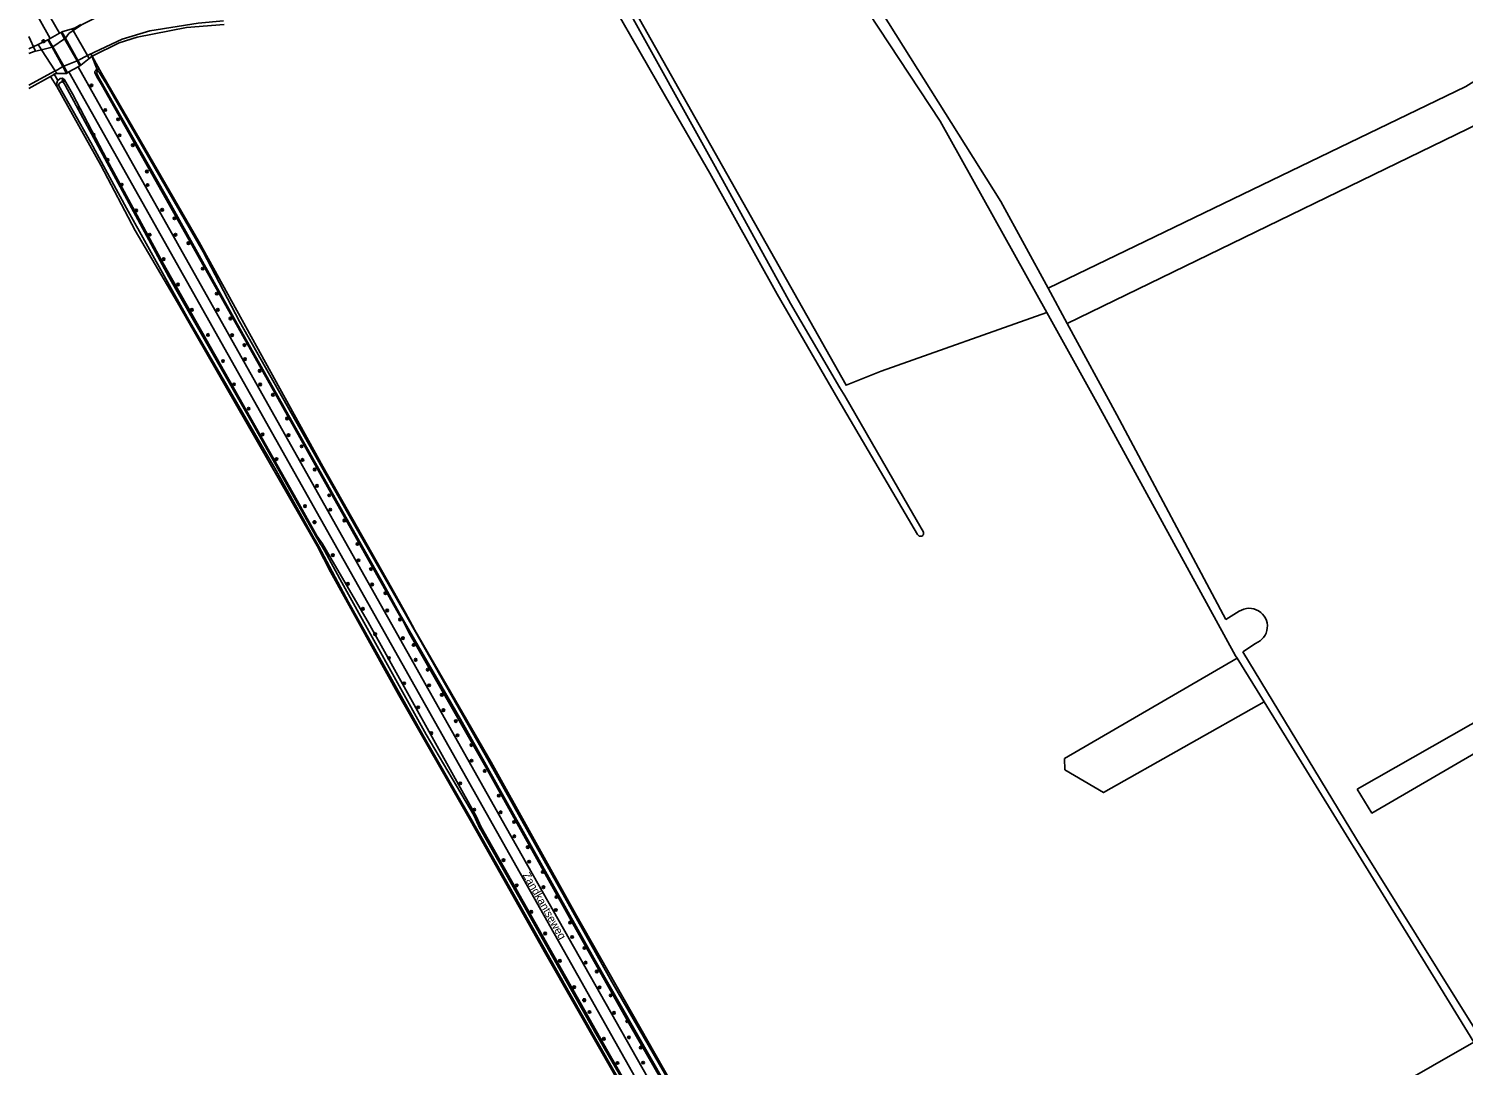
# Model space of a CAD drawing. Extents: x 140000 to 143000, y 403500 to 406000.
# Drawn here: x 140000 to 140448.3, y 404957.2 to 405281.2 of the extents above; entities that cross this region are included whole.
import ezdxf

# ---------------------------------------------------------------- set-up
doc = ezdxf.new("R2010")
doc.units = 0
for name, color, linetype in [('gg-anno-openbare ruimte label', 7, 'Continuous'), ('gg-knt-bronhoudergrens', 7, 'Continuous'), ('gg-knt-verharding', 7, 'Continuous'), ('gg-kntw-bovenkant insteek waterloop', 7, 'Continuous'), ('gg-kntw-waterlijn', 7, 'Continuous'), ('gg-kwrk-duiker nz buis', 7, 'Continuous'), ('gg-kwrk-kunstwerk niveau 01', 7, 'Continuous'), ('gt-grn-groengrens', 7, 'Continuous'), ('gt-grn-vlakafsluiter', 7, 'Continuous'), ('gt-symb-boom', 7, 'Continuous'), ('gt-symb-lichtmast', 7, 'Continuous')]:
    doc.layers.add(name, color=color, linetype=linetype)

# ---------------------------------------------------------------- blocks, each defined once
blk = doc.blocks.new('gt0-BOOM')
at = {"layer": 'gt-symb-boom'}
for radius in [0.4, 0.2]:
    blk.add_circle((0, 0), radius, dxfattribs=at)
blk = doc.blocks.new('gt0-LMAST')
at = {"layer": 'gt-symb-lichtmast'}
for p, q in [((-0.18, 0.17), (-0.45, 0.44)), ((-0.01, 0.25), (-0.01, 0.62)), ((0.17, 0.17), (0.44, 0.44)), ((-0.26, 0), (-0.63, 0)), ((-0.18, -0.18), (-0.45, -0.45)), ((-0.01, -0.25), (-0.01, -0.63)), ((0.44, -0.45), (0.17, -0.18)), ((0.24, 0), (0.62, 0))]:
    blk.add_line(p, q, dxfattribs=at)
blk.add_circle((-0.01, 0), 0.25, dxfattribs=at)

msp = doc.modelspace()

# ---------------------------------------------------------------- linework, layer by layer
at = {"layer": 'gg-knt-bronhoudergrens'}
msp.add_lwpolyline([(140318.13, 405192.44), (140266.36, 405174.11), (140255.39, 405169.74), (140185.81, 405293.12)], dxfattribs=at)
at = {"layer": 'gg-knt-verharding'}
msp.add_line((140000, 405296.57), (140009.61, 405279.74), dxfattribs=at)
for points in [[(140000, 405290.13), (140000.13, 405289.9), (140006.7, 405278.1)], [(140012.59, 405267.65), (140091.15, 405127.98), (140215.94, 404906.42), (140216.06, 404906.21)], [(140015.47, 405269.29), (140093.98, 405129.51), (140149.27, 405031.32), (140217.82, 404910.2), (140257.23, 404841.36), (140317.65, 404734.89), (140320.04, 404730.7)]]:
    msp.add_lwpolyline(points, dxfattribs=at)
at = {"layer": 'gg-kntw-bovenkant insteek waterloop'}
for p, q in [((140013.55, 405281.15), (140010.35, 405280.16)), ((140000, 405274.88), (140002.93, 405276.26)), ((140006, 405277.71), (140002.93, 405276.26)), ((140018.93, 405271.88), (140016.25, 405269.74)), ((140018.93, 405271.88), (140019.85, 405272.61)), ((140008.79, 405267.16), (140011.83, 405267.22)), ((140000, 405262.5), (140006.86, 405266.27)), ((140324.5, 405189.04), (140318.52, 405200.05)), ((140378.27, 405099.07), (140374.07, 405096.51)), ((140383.36, 405089.05), (140379.37, 405086.39)), ((140377.62, 405084.38), (140386.05, 405070.72))]:
    msp.add_line(p, q, dxfattribs=at)
for points in [[(140185.79, 405289.85), (140214.49, 405238.1), (140238.07, 405195.27), (140253.46, 405168.97), (140254.97, 405166.39), (140274.97, 405131.7), (140279.57, 405123.84)], [(140259.14, 405291.24), (140284.8, 405252.29), (140318.13, 405192.44)], [(140318.52, 405200.05), (140303.79, 405227.18), (140262.3, 405293.17)], [(140182.97, 405287.93), (140199.02, 405259.94), (140212.81, 405235.99), (140233.91, 405198.18), (140252.83, 405165.48), (140277.77, 405123.12)], [(140016.26, 405282.49), (140014.56, 405281.47), (140013.55, 405281.15)], [(140061.04, 405282.49), (140049.32, 405281.51), (140033.9, 405278.48), (140028.3, 405276.8), (140019.85, 405272.61)], [(140008.79, 405267.16), (140008.45, 405267.15), (140006.86, 405266.27)], [(140221.32, 404915.12), (140221.27, 404914.79), (140221.05, 404914.55), (140220.48, 404914.22), (140219.96, 404914.32), (140219.52, 404914.81), (140187.96, 404969.55), (140169.57, 405002.2), (140142.8, 405050.33), (140118.75, 405092.41), (140116.73, 405096.57), (140115.86, 405097.86), (140114.98, 405099.37), (140049.1, 405216.97), (140022.7, 405263.69), (140021.65, 405265.62), (140020.77, 405267.14)], [(140022.22, 405268.24), (140023.21, 405266.5), (140053.29, 405214.48), (140091.86, 405144.38), (140113.34, 405106.43), (140117.71, 405098.64), (140120.4, 405093.58), (140120.66, 405093.21), (140144.47, 405051.89), (140170.87, 405004.52), (140206.08, 404942.46), (140221.32, 404915.12)], [(140211.16, 404908.87), (140180.94, 404961.44), (140141.23, 405031.76), (140139.9, 405034.84), (140106.05, 405095.67), (140094.79, 405114.98), (140091.84, 405120.15), (140090.08, 405122.65), (140083.85, 405133.69), (140065.63, 405166.05), (140041.91, 405207.98), (140024.47, 405240.13), (140013.65, 405260.82), (140011.23, 405265.23), (140010.6, 405265.67), (140009.82, 405265.58), (140008.99, 405264.87), (140008.83, 405264.18), (140008.78, 405263.08)], [(140211.16, 404908.87), (140211.14, 404908.72), (140210.91, 404908.37), (140210.58, 404908.25), (140209.72, 404908.53), (140209.26, 404908.96), (140187.27, 404946.74), (140161.57, 404991.94), (140139.8, 405030.55), (140137.59, 405034.4), (140115.65, 405072.87), (140094.35, 405111.42), (140090.14, 405119.58), (140088.48, 405122.42), (140067.9, 405158.36), (140046.49, 405195.64), (140033.29, 405218.1), (140022.54, 405238.57), (140008.78, 405263.08)], [(140318.13, 405192.44), (140334.31, 405163.38), (140377.12, 405085.2), (140377.62, 405084.38)], [(140374.07, 405096.51), (140340, 405160.5), (140324.5, 405189.04)], [(140415.14, 405043.52), (140419.73, 405036), (140553.77, 405113.96), (140550.4, 405120.5), (140415.14, 405043.52)], [(140458.74, 404957.51), (140414.93, 405027.89), (140379.37, 405086.39)], [(140386.05, 405070.72), (140441.18, 404981.34), (140451.59, 404964.43)]]:
    msp.add_lwpolyline(points, dxfattribs=at)
for centre, radius, start, end in [((140021.62, 405267.53), 0.931, 49.8036, 204.2643), ((140278.67, 405123.48), 0.969, 201.7195, 22.1689), ((140381.38, 405094.35), 5.66, 290.4682, 123.3593)]:
    msp.add_arc(centre, radius, start, end, dxfattribs=at)
at = {"layer": 'gg-kntw-waterlijn'}
for p, q in [((140011.22, 405278.06), (140007.51, 405275.54)), ((140011.45, 405278.22), (140011.22, 405278.06)), ((140007.29, 405275.39), (140007.51, 405275.54)), ((140018.4, 405272.79), (140015.4, 405271.24)), ((140000, 405263.48), (140008.28, 405267.96)), ((140010.63, 405269.38), (140010.93, 405269.49)), ((140015.12, 405271.13), (140010.93, 405269.49)), ((140015.4, 405271.24), (140015.12, 405271.13))]:
    msp.add_line(p, q, dxfattribs=at)
for points in [[(140013.88, 405280.59), (140016.68, 405282.5), (140025.77, 405287.06), (140031.9, 405289.57), (140037.84, 405290.93), (140043.97, 405291.59), (140059.66, 405293)], [(140013.88, 405280.59), (140012.58, 405279.71), (140011.45, 405278.22)], [(140060.89, 405283.64), (140052.99, 405282.92), (140037.9, 405280.55), (140029.18, 405277.93), (140018.74, 405272.96), (140018.4, 405272.79)], [(140000, 405273.41), (140001.74, 405274.04), (140003.99, 405274.61)], [(140007.29, 405275.39), (140004.4, 405274.71), (140003.99, 405274.61)], [(140008.28, 405267.96), (140009.01, 405268.35), (140010.63, 405269.38)], [(140021.26, 405267.2), (140022.12, 405265.46), (140042.95, 405228.87), (140064.57, 405189.87), (140110.88, 405107.52), (140115.91, 405098.42), (140134.92, 405065.37), (140176.54, 404990.61), (140216.26, 404920.9)], [(140205.32, 404943.14), (140182.22, 404983.23), (140170.55, 405004.24), (140143.62, 405052.54), (140117.28, 405098.93), (140102.42, 405125), (140065.87, 405189.67), (140054.52, 405211.46), (140024.13, 405264.24), (140022.99, 405266.02), (140022.01, 405267.6)], [(140097.86, 405108.06), (140092.52, 405117.91), (140091.45, 405119.68), (140091.2, 405120.01), (140089.63, 405122.72), (140070.21, 405157.24), (140051.52, 405190.03), (140043.76, 405203.58), (140011.44, 405263.52), (140010.88, 405264.4), (140010.4, 405264.57), (140009.71, 405264.22), (140009.35, 405263.68), (140009.46, 405263.32), (140013.85, 405255.35), (140019.42, 405245.61), (140030.56, 405225.12), (140049.52, 405190.99), (140077.3, 405143.07), (140088.79, 405122.6), (140090.71, 405119.35), (140099.9, 405101.97), (140123.11, 405060.43), (140137.75, 405035.07), (140140.34, 405030.47), (140169.09, 404979.57), (140205.29, 404915.94)], [(140209.96, 404910.55), (140177.2, 404967.09), (140154.54, 405007.43), (140141.24, 405030.75), (140140.98, 405031.17), (140139.1, 405035.32), (140124.19, 405060.58), (140097.86, 405108.06)]]:
    msp.add_lwpolyline(points, dxfattribs=at)
msp.add_arc((140021.64, 405267.4), 0.426, 28.7292, 208.1271, dxfattribs=at)
at = {"layer": 'gg-kwrk-duiker nz buis'}
for p, q in [((140000, 405278.69), (140002.02, 405274.39)), ((140021.65, 405267.94), (140019.42, 405273.45)), ((140009.15, 405264.95), (140007.84, 405267.14))]:
    msp.add_line(p, q, dxfattribs=at)
at = {"layer": 'gg-kwrk-kunstwerk niveau 01'}
for p, q in [((140006.21, 405277.83), (140006, 405277.71)), ((140006, 405277.71), (140007.29, 405275.39)), ((140006.21, 405277.83), (140006.7, 405278.1)), ((140006.21, 405277.83), (140007.51, 405275.54)), ((140009.61, 405279.74), (140006.7, 405278.1)), ((140010.12, 405280.03), (140009.61, 405279.74)), ((140010.35, 405280.16), (140010.12, 405280.03)), ((140010.12, 405280.03), (140011.22, 405278.06)), ((140011.45, 405278.22), (140010.35, 405280.16)), ((140011.22, 405278.06), (140015.12, 405271.13)), ((140015.4, 405271.24), (140011.45, 405278.22)), ((140007.29, 405275.39), (140010.63, 405269.38)), ((140010.93, 405269.49), (140007.51, 405275.54)), ((140010.63, 405269.38), (140011.83, 405267.22)), ((140012.12, 405267.39), (140010.93, 405269.49)), ((140011.83, 405267.22), (140012.12, 405267.39)), ((140012.12, 405267.39), (140012.59, 405267.65)), ((140012.59, 405267.65), (140015.47, 405269.29)), ((140015.99, 405269.59), (140015.12, 405271.13)), ((140016.25, 405269.74), (140015.4, 405271.24)), ((140015.99, 405269.59), (140015.47, 405269.29)), ((140015.99, 405269.59), (140016.25, 405269.74))]:
    msp.add_line(p, q, dxfattribs=at)
at = {"layer": 'gt-grn-groengrens'}
for p, q in [((140019.85, 405272.61), (140022.22, 405268.24)), ((140008.78, 405263.08), (140006.86, 405266.27))]:
    msp.add_line(p, q, dxfattribs=at)
for points in [[(140318.52, 405200.05), (140449.03, 405263.08), (140470.77, 405276.7)], [(140324.5, 405189.04), (140475.43, 405262.4), (140592.61, 405062.34), (140590.84, 405060.78), (140635.63, 404986.82), (140632.67, 404984.58)], [(140377.62, 405084.38), (140323.61, 405053.04), (140323.73, 405049.52), (140335.81, 405042.41), (140386.05, 405070.72)], [(140451.59, 404964.43), (140399.93, 404934.76), (140396.8, 404929.18), (140435.78, 404864.65), (140439.27, 404862.52), (140496.9, 404890.71)]]:
    msp.add_lwpolyline(points, dxfattribs=at)
at = {"layer": 'gt-grn-vlakafsluiter'}
for p, q in [((140013.55, 405281.15), (140013.88, 405280.59)), ((140013.88, 405280.59), (140018.4, 405272.79)), ((140003.99, 405274.61), (140002.93, 405276.26)), ((140003.99, 405274.61), (140008.28, 405267.96)), ((140018.4, 405272.79), (140018.93, 405271.88)), ((140008.28, 405267.96), (140008.79, 405267.16))]:
    msp.add_line(p, q, dxfattribs=at)

# ---------------------------------------------------------------- block references
at = {"layer": 'gt-symb-boom'}
for p in [(140010.84, 405265.03), (140019.61, 405263.45), (140015.6, 405256.41), (140023.94, 405255.78), (140027.96, 405252.83), (140020.29, 405248.02), (140028.41, 405247.86), (140032.52, 405244.75), (140024.61, 405240.19), (140036.95, 405236.55), (140029.08, 405232.4), (140037.15, 405232.33), (140033.58, 405224.34), (140041.72, 405224.58), (140045.56, 405221.91), (140037.82, 405216.8), (140045.86, 405216.77), (140049.9, 405214.14), (140042.17, 405209.16), (140054.37, 405206.16), (140046.64, 405201.23), (140058.77, 405198.36), (140050.96, 405193.28), (140059.07, 405193.32), (140063.05, 405190.57), (140056.01, 405185.46), (140063.55, 405185.37), (140067.42, 405182.29), (140060.73, 405177.29), (140067.58, 405177.89), (140072.17, 405174.24), (140064.14, 405170.03), (140072.34, 405169.96), (140076.32, 405166.75), (140068.73, 405162.41), (140080.7, 405159.33), (140073.12, 405154.36), (140081.2, 405154.13), (140085.29, 405150.65), (140077.42, 405146.65), (140085.55, 405146.38), (140089.36, 405143.38), (140090.09, 405138.3), (140093.91, 405135.31), (140086.34, 405131.95), (140094.24, 405130.83), (140098.61, 405127.43), (140102.71, 405120.11), (140095.03, 405116.61), (140103.06, 405115.01), (140106.94, 405112.27), (140099.72, 405107.65), (140107.3, 405107.44), (140111.49, 405104.73), (140104.43, 405099.86), (140111.99, 405099.3), (140116.03, 405096.52), (140108.26, 405091.92), (140116.93, 405090.66), (140120.27, 405088.56), (140112.57, 405084.45), (140120.91, 405083.92), (140124.65, 405080.8), (140117.32, 405076.55), (140125.12, 405075.92), (140129.07, 405072.97), (140121.7, 405069.06), (140129.58, 405068.17), (140125.81, 405060.99), (140133.46, 405064.75), (140133.98, 405060.29), (140138.3, 405057.26), (140138.39, 405052.38), (140142.49, 405049.17), (140134.87, 405045.29), (140146.92, 405041.44), (140139.26, 405037.06), (140147.48, 405036.25), (140151.63, 405033.2), (140151.75, 405028.75), (140155.94, 405025.36), (140148.37, 405021.3), (140156.39, 405020.8), (140160.61, 405017.6), (140152.5, 405013.39), (140160.83, 405012.82), (140164.87, 405009.77), (140157.05, 405005.13), (140164.73, 405005.69), (140161.37, 404998.35), (140169.15, 405001.77), (140169.83, 404997.27), (140173.69, 404993.84), (140165.96, 404989.81), (140174.02, 404989.26), (140177.5, 404986.48), (140170.44, 404981.59), (140178.39, 404981.5), (140181.87, 404979), (140175.21, 404973.82), (140182.9, 404973.56), (140187.03, 404970.89), (140179.73, 404965.45), (140187.55, 404965.88), (140191.24, 404962.69), (140183.96, 404957.88), (140192, 404957.98)]:
    msp.add_blockref('gt0-BOOM', p, dxfattribs=at)
at = {"layer": 'gt-symb-lichtmast'}
for p in [(140004.62, 405277.26), (140089.31, 405126.94), (140173.62, 404977.54)]:
    msp.add_blockref('gt0-LMAST', p, dxfattribs=at)

# ---------------------------------------------------------------- texts
at = {"layer": 'gg-anno-openbare ruimte label'}
msp.add_text('Zandkantseweg', height=2.5, rotation=299.7, dxfattribs=at).set_placement((140154.24, 405016.67))

doc.saveas('drawing.dxf')
